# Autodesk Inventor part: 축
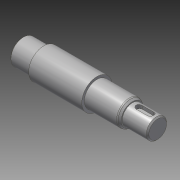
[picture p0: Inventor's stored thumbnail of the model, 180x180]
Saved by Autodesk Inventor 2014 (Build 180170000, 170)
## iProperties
Created: 2016-06
Part Number: 축
Material: 강철, 연강
Document SubType Name: Modeling
Designer: mduedu
Density: 7.86 g/cm^3
Appearance: 강철
Author: mduedu
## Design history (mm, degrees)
sketch "스케치1"
  geometry: L1 (-53.5, 0)-(53.5, 0); L2 (-53.5, 0)-(-53.5, 10); L3 (-53.5, 10)-(-36.5, 10); L4 (-36.5, 10)-(-36.5, 12); L5 (-36.5, 12)-(5.5, 12); L6 (5.5, 12)-(5.5, 10); L7 (5.5, 10)-(33.5, 10); L8 (33.5, 10)-(33.5, 8); L9 (33.5, 8)-(53.5, 8); L10 (53.5, 8)-(53.5, 0); 2 further points
  constraints: 20 end point, 5 parallel, 2 perpendicular, 1 coincident, 1 collinear, 1 horizontal, 1 midpoint, 1 vertical
  dimensions: "d0" = 107 distance of L1.start L1.end; "d2" = 16 diameter of L9 L1; "d3" = 20 diameter of L7 L1; "d4" = 24 diameter of L5 L1; "d5" = 20 diameter of L3 L1; "d6" = 17 distance of L2.end L3.end; "d7" = 20 distance of L8.end L9.end; "d8" = 48 distance from line of L5.end L10
revolve "회전1" sketch "스케치1" stored, may be unused: angle "d9" = 90 deg
chamfer "모따기1" distance "d10" = 2; stored, may be unused: second distance "d11" = 2, angle "d12" = 30 deg
fillet "모깎기1" dims "d13" = 2
node "작업 평면1"
sketch "스케치2"
  geometry: L1 (-4.5, 2.5)-(4.5, 2.5); L2 (4.5, -2.5)-(-4.5, -2.5); L3 (-4.5, 0)-(4.5, 0); L4 (-10, 8.845)-(-10, -8.845) reference; A1 r 2.5 centre (-4.5, 0) between (-4.5, 2.5) and (-4.5, -2.5); A2 r 2.5 centre (4.5, 0) between (4.5, -2.5) and (4.5, 2.5); 1 further point
  constraints: 6 end point, 4 point on circle, 3 tangent, 2 centre point, 2 parallel, 1 horizontal, 1 horizontal alignment
  dimensions: "d14" = 3 distance edge to line of A1 L4; "d15" = 5 distance between parallel lines of L2 L1; "d16" = 14 dimension on A2 A1
extrude "돌출1" cut sketch "스케치2" distance "d17" = 3; taper "d18" = 0 deg
chamfer "모따기2" distance "d19" = 1; stored, may be unused: second distance "d20" = 2, angle "d21" = 30 deg
sketch "스케치3"
  geometry: L1 (-33.5, -8)-(-52.5, -8) reference; L2 (-53.5, -7)-(-53.5, 7) reference; L3 (-36, -8)-(-37.5, -6.5); L4 (-37.5, -6.5)-(-37.5, -8); L5 (-36, -8)-(-37.5, -8); 1 further point
  constraints: 6 end point, 2 point on line, 1 collinear, 1 vertical
  dimensions: "d22" = 45 deg angle of L4 L3; "d23" = 16 distance between parallel lines of L2 L4; "d24" = 3 diameter of L3.start L4
revolve "회전2" stored, may be unused: angle "d25" = 90 deg
node "작업점1"
sketch "스케치4"
  geometry: 1 further point
hole "구멍1" sketch "스케치4" at (0, 0) diameter "d26" = 3.242; stored, may be unused: countersink angle "d30" = 90 deg, drill point angle "d32" = 120 deg; dims "d27" = 8, "d28" = 4, "d29" = 2, "d31" = 11
chamfer "모따기3" distance "d33" = 2; stored, may be unused: second distance "d34" = 2, angle "d35" = 30 deg
node "솔리드1"
